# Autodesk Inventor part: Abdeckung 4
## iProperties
Shininess: 64.0
Length Units: 11269
Angle Units: 11279
Time Units: 11290
Mass Units: 11283
Length Display Precision: 3
Angle Display Precision: 2
Compacted: True
Part Number: Abdeckung 4
Document SubType Name: Sheet Metal
Created: 2005-02
Material: Nichtrostender Stahl (austenitisch)
Designer: Administrator
Manufacturer: Standard
Standards Organization: Custom
Density: 0.0
Volumn: 0.0
Area: 0.0
PropertySet Name: Model Information
Control State: 0
Master: False
Checked Out: False
Author: Administrator
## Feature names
1. Platte1
2. Platte2
3. Biegung1
4. Platte3
5. Biegung2
6. Platte4
7. Biegung3
8. Platte5
9. Biegung4
10. Platte6
11. Biegung5
12. Platte7
13. Biegung6
14. Platte8
15. Biegung7
16. Platte9
17. Biegung8
18. ExtrusionAbwicklung1
19. Ecke1
20. Ecke2
21. Ecke3
22. Ecke4
23. Ausklinkung1
24. Ecke5
25. Ecke6
26. Ecke7
27. Ausklinkung2
28. Ausklinkung3
29. Ecke8
